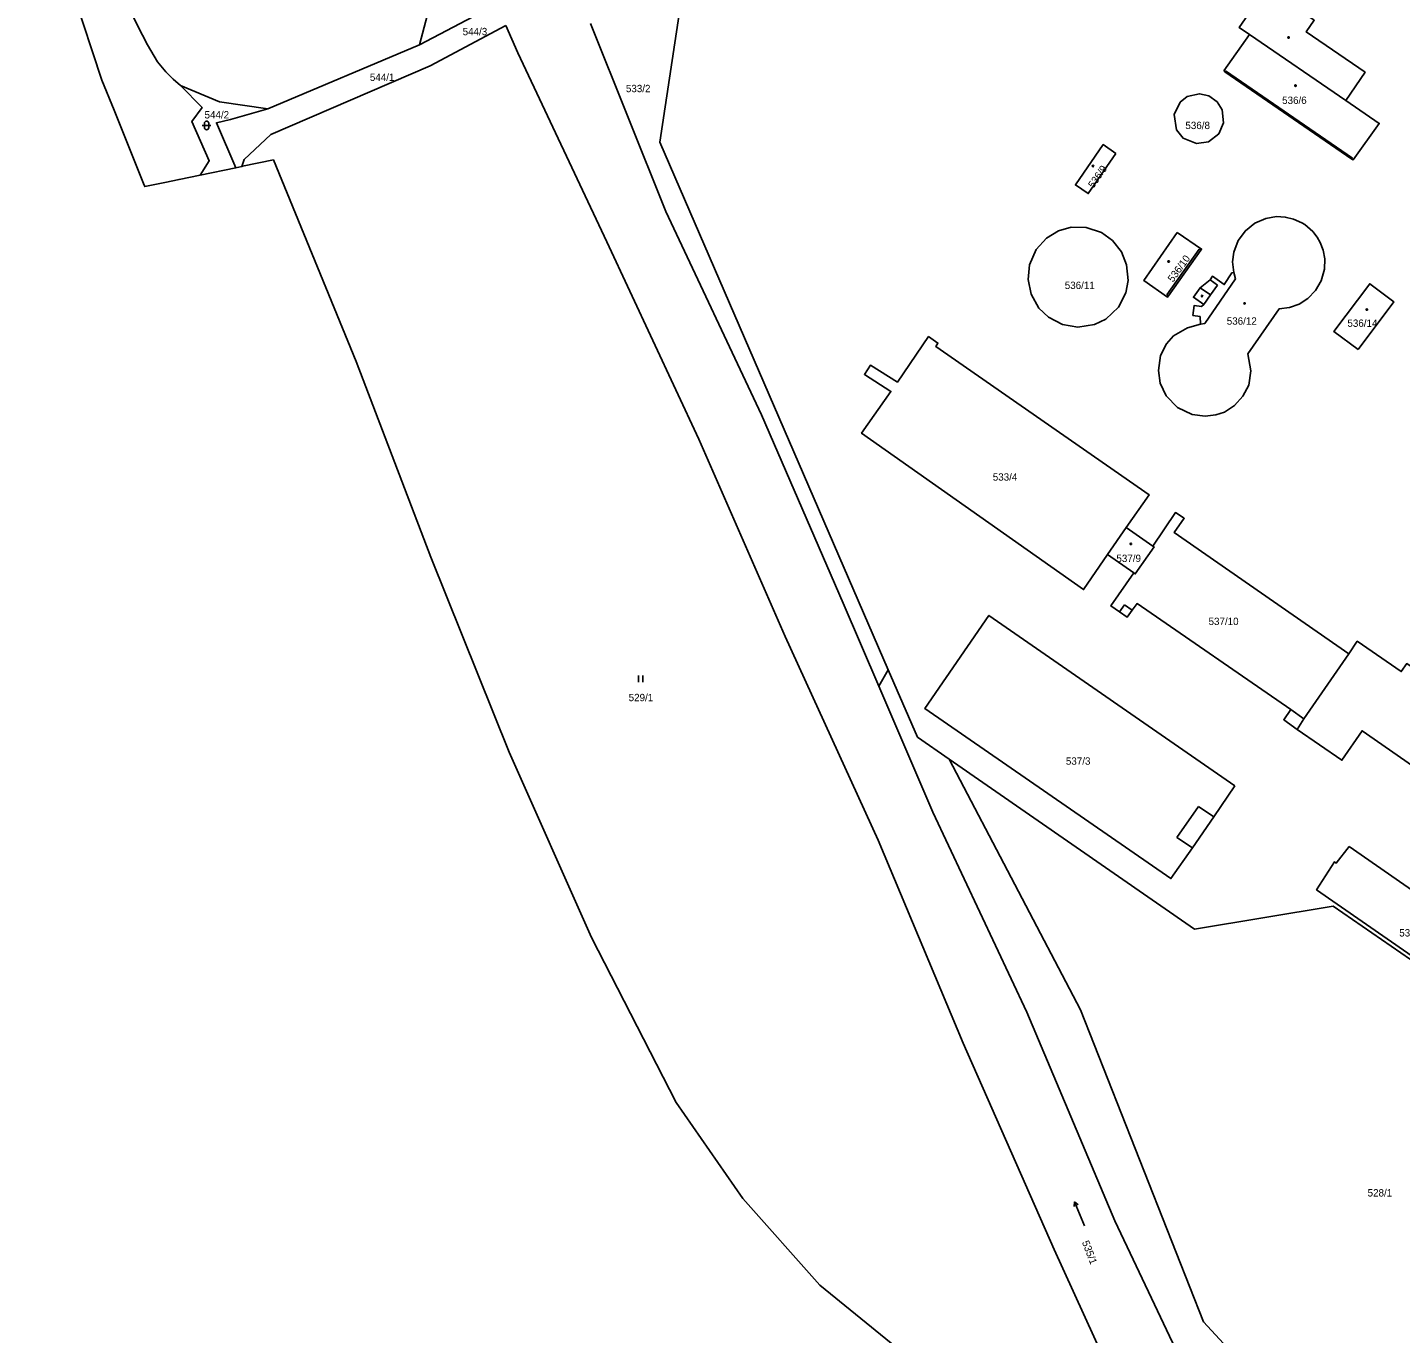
# Model space of a CAD drawing. Extents: x -757266 to -753360, y -1162585 to -1157740.
# Drawn here: x -756709.6 to -756391.6, y -1161803.6 to -1161501.2 of the extents above; entities that cross this region are included whole.
import ezdxf

# ---------------------------------------------------------------- set-up
doc = ezdxf.new("R2010")
doc.units = 0
for name, color, linetype in [('Hranice kat_území', 7, 'Continuous'), ('Hranice parcel', 7, 'Continuous'), ('Parcelní čísla', 7, 'Continuous'), ('Vnitřní kresba', 7, 'Continuous'), ('Značky budov', 7, 'Continuous'), ('Značky kultur', 7, 'Continuous')]:
    doc.layers.add(name, color=color, linetype=linetype)

msp = doc.modelspace()

# ---------------------------------------------------------------- linework, layer by layer
at = {"layer": 'Hranice kat_území'}
msp.add_lwpolyline([(-756705.49, -1161473.54), (-756692.4, -1161513.44), (-756689.53, -1161520.37), (-756682.73, -1161537.36), (-756682.45, -1161538.05), (-756677.8, -1161537.09), (-756674.5, -1161536.4), (-756669.59, -1161535.39), (-756661.38, -1161533.69), (-756659.97, -1161533.4), (-756659.78, -1161533.36), (-756652.63, -1161531.88), (-756633.52, -1161578.59), (-756616.19, -1161623.87), (-756598.04, -1161669), (-756578.96, -1161711.91), (-756559.4, -1161750.12), (-756543.9, -1161772.36), (-756526.13, -1161792.42), (-756501.3, -1161812.53)], dxfattribs=at)
at = {"layer": 'Hranice parcel'}
for p, q in [((-756661.38, -1161533.69), (-756669.59, -1161535.39)), ((-756661.38, -1161533.69), (-756659.97, -1161533.4)), ((-756459.47, -1161623.24), (-756455.15, -1161617)), ((-756455.15, -1161617), (-756449.01, -1161621.28)), ((-756453.34, -1161627.49), (-756459.47, -1161623.24)), ((-756512.46, -1161653.75), (-756510.26, -1161649.92))]:
    msp.add_line(p, q, dxfattribs=at)
for points in [[(-756705.19, -1161454.84), (-756689.73, -1161487.77), (-756688.29, -1161491.6), (-756686.38, -1161496.2), (-756684.14, -1161500.75), (-756681.78, -1161505.2), (-756679.51, -1161509.19), (-756677.58, -1161511.45), (-756675.83, -1161513.16), (-756674.17, -1161514.67)], [(-756709.61, -1161464.59), (-756705.49, -1161473.54), (-756692.4, -1161513.44)], [(-756510.26, -1161649.92), (-756563.14, -1161527.74), (-756558.03, -1161493.93)], [(-756432.53, -1161511.28), (-756426.61, -1161502.85), (-756428.99, -1161501.19), (-756424.46, -1161494.61), (-756421.81, -1161496.44), (-756419.95, -1161493.81), (-756411.59, -1161499.53), (-756413.45, -1161502.24), (-756399.82, -1161511.57), (-756404.28, -1161518.1), (-756396.55, -1161523.42), (-756402.6, -1161531.88), (-756402.85, -1161531.71), (-756432.29, -1161511.45), (-756432.53, -1161511.28)], [(-756653.91, -1161520.08), (-756618.83, -1161505.23), (-756600.13, -1161495.47), (-756599.68, -1161495.24)], [(-756579.23, -1161500.29), (-756561.73, -1161543.82), (-756539.64, -1161590.93), (-756520.71, -1161634.54), (-756512.46, -1161653.75)], [(-756598.79, -1161500.79), (-756616.34, -1161510.09), (-756653.26, -1161525.99), (-756659.39, -1161531.76), (-756659.97, -1161533.4)], [(-756406.05, -1161891.27), (-756403.92, -1161889.19), (-756422.71, -1161865.72), (-756443.95, -1161842.26), (-756451.04, -1161829.66), (-756471.86, -1161784.15), (-756492.92, -1161736.36), (-756512.6, -1161689.34), (-756534.1, -1161642.21), (-756554.15, -1161596.51), (-756575.39, -1161550.85), (-756596.01, -1161507.08), (-756598.79, -1161500.79)], [(-756692.4, -1161513.44), (-756689.53, -1161520.37), (-756682.73, -1161537.36), (-756682.45, -1161538.05), (-756677.8, -1161537.09), (-756674.5, -1161536.4), (-756669.59, -1161535.39)], [(-756653.91, -1161520.08), (-756665.16, -1161518.44), (-756674.17, -1161514.67)], [(-756674.17, -1161514.67), (-756669.18, -1161519.74), (-756671.58, -1161522.96), (-756667.52, -1161532.13), (-756669.59, -1161535.39)], [(-756444.01, -1161521.34), (-756442.65, -1161518.54), (-756440.99, -1161517.23), (-756438.16, -1161516.57), (-756435.97, -1161517.07), (-756434.1, -1161518.4), (-756432.93, -1161520.32), (-756432.62, -1161523.32), (-756433.69, -1161525.81), (-756436.06, -1161527.66), (-756438.89, -1161528.1), (-756441.98, -1161526.82), (-756443.49, -1161524.92), (-756444.01, -1161521.34)], [(-756653.91, -1161520.08), (-756662.59, -1161522.51), (-756665.85, -1161523.27), (-756661.38, -1161533.69)], [(-756457.52, -1161530.41), (-756463.95, -1161539.67), (-756466.9, -1161537.65), (-756460.45, -1161528.34), (-756457.52, -1161530.41)], [(-756652.63, -1161531.88), (-756659.78, -1161533.36), (-756659.97, -1161533.4)], [(-756469.44, -1161834.41), (-756501.3, -1161812.53), (-756526.13, -1161792.42), (-756543.9, -1161772.36), (-756559.4, -1161750.12), (-756578.96, -1161711.91), (-756598.04, -1161669), (-756616.19, -1161623.87), (-756633.52, -1161578.59), (-756652.63, -1161531.88)], [(-756455.05, -1161556.17), (-756454.7, -1161559.78), (-756455.22, -1161562.63), (-756456.91, -1161565.97), (-756459.89, -1161568.77), (-756462.5, -1161570.02), (-756466.35, -1161570.59), (-756469.87, -1161569.99), (-756473.15, -1161568.31), (-756475.35, -1161566.23), (-756477.16, -1161562.99), (-756477.86, -1161559.53), (-756477.52, -1161556.16), (-756475.98, -1161552.64), (-756473.62, -1161550), (-756470.85, -1161548.31), (-756467.85, -1161547.47), (-756464.4, -1161547.51), (-756460.89, -1161548.69), (-756458.33, -1161550.55), (-756456.25, -1161553.2), (-756455.05, -1161556.17)], [(-756443.25, -1161589.18), (-756445.87, -1161586.52), (-756447.28, -1161583.54), (-756447.67, -1161580.67), (-756447.16, -1161577.2), (-756445.77, -1161574.45), (-756444.15, -1161572.58), (-756440.97, -1161570.72), (-756437.91, -1161569.88), (-756438.04, -1161568.14), (-756439.7, -1161567.9), (-756439.38, -1161565.56), (-756437.72, -1161565.78), (-756437.2, -1161565.34), (-756439.57, -1161563.68), (-756438.03, -1161561.48), (-756435.73, -1161559.63), (-756435.16, -1161558.8), (-756432.45, -1161560.73), (-756430.7, -1161558.04), (-756430.24, -1161557.94), (-756430.49, -1161555.44), (-756430.2, -1161553.25), (-756429.2, -1161550.57), (-756427.55, -1161548.29), (-756425.35, -1161546.53), (-756422.8, -1161545.42), (-756420.33, -1161545.01), (-756418.32, -1161545.12), (-756416.42, -1161545.56), (-756414.43, -1161546.41), (-756413.75, -1161546.85), (-756411.94, -1161548.43), (-756410.9, -1161549.76), (-756410.21, -1161550.99), (-756409.49, -1161552.78), (-756409.12, -1161554.78), (-756409.22, -1161557.17), (-756409.98, -1161559.88), (-756411.29, -1161562.15), (-756413.06, -1161563.99), (-756415.07, -1161565.26), (-756417.3, -1161566.07), (-756419.75, -1161566.39), (-756426.95, -1161576.81), (-756426.28, -1161580.73), (-756426.76, -1161584.06), (-756428.11, -1161586.6), (-756430.06, -1161588.76), (-756432.37, -1161590.26), (-756434.36, -1161590.93), (-756436.83, -1161591.24), (-756439.85, -1161590.86), (-756443.25, -1161589.18)], [(-756443.33, -1161548.72), (-756437.7, -1161552.54), (-756437.89, -1161552.81), (-756445.38, -1161563.37), (-756445.57, -1161563.64), (-756451.09, -1161559.77), (-756443.33, -1161548.72)], [(-756401.44, -1161575.8), (-756407.02, -1161571.62), (-756398.74, -1161560.55), (-756393.13, -1161564.74), (-756401.44, -1161575.8)], [(-756455.15, -1161617), (-756449.85, -1161609.39), (-756499.23, -1161575.1), (-756498.76, -1161574.29), (-756500.9, -1161572.8), (-756508.12, -1161583.3), (-756514.34, -1161579.39), (-756515.77, -1161581.53), (-756509.63, -1161585.49), (-756516.41, -1161595.17), (-756465.01, -1161631.37), (-756459.47, -1161623.24)], [(-756449.01, -1161621.28), (-756443.75, -1161613.53), (-756441.71, -1161614.85), (-756444.03, -1161618.17), (-756403.55, -1161646.22)], [(-756453.34, -1161627.49), (-756453.03, -1161627.72), (-756448.7, -1161621.5), (-756449.01, -1161621.28)], [(-756415.55, -1161663.73), (-756418.66, -1161661.5), (-756417.04, -1161659.12), (-756452.61, -1161634.62), (-756453.77, -1161636.14), (-756454.88, -1161637.71), (-756456.67, -1161636.49), (-756458.7, -1161635.14), (-756453.34, -1161627.49)], [(-756429.98, -1161676.77), (-756434.82, -1161684), (-756439.81, -1161691.19), (-756444.79, -1161698.28), (-756501.81, -1161658.88), (-756486.94, -1161637.35), (-756429.98, -1161676.77)], [(-756403.55, -1161646.22), (-756401.63, -1161643.34), (-756391.45, -1161650.36), (-756390.15, -1161648.48), (-756373.68, -1161659.86), (-756371.23, -1161656.38), (-756366.82, -1161659.39), (-756369.21, -1161662.95), (-756349.76, -1161676.41), (-756360.41, -1161691.89), (-756400.5, -1161664.05), (-756405.19, -1161670.87), (-756415.55, -1161663.73)], [(-756403.55, -1161646.22), (-756413.98, -1161661.26), (-756415.55, -1161663.73)], [(-756510.26, -1161649.92), (-756503.51, -1161665.52), (-756496.18, -1161670.6)], [(-756394.07, -1161877.95), (-756411.35, -1161855.64), (-756427.03, -1161838.58), (-756437.34, -1161820.63), (-756457.78, -1161777.52), (-756478.19, -1161729.21), (-756499.94, -1161682.92), (-756512.46, -1161653.75)], [(-756496.18, -1161670.6), (-756465.75, -1161728.65), (-756437.23, -1161800.9), (-756431.67, -1161806.91), (-756424.75, -1161806.95), (-756415.81, -1161824.54), (-756417.35, -1161828.46), (-756403.52, -1161852.63), (-756390.1, -1161864.08), (-756386.3, -1161867.32)], [(-756376.45, -1161723.95), (-756378.08, -1161724.72), (-756407.17, -1161704.66), (-756439.3, -1161710.01), (-756496.18, -1161670.6)], [(-756403.49, -1161690.82), (-756371.84, -1161712.83), (-756374.43, -1161716.92), (-756374.03, -1161717.21), (-756378.36, -1161723.56), (-756411.05, -1161700.86), (-756406.92, -1161694.42), (-756406.53, -1161694.73), (-756403.49, -1161690.82)]]:
    msp.add_lwpolyline(points, dxfattribs=at)
at = {"layer": 'Vnitřní kresba'}
for p, q in [((-756615.95, -1161494.39), (-756618.83, -1161505.23)), ((-756426.61, -1161502.85), (-756404.28, -1161518.1)), ((-756432.29, -1161511.45), (-756432.14, -1161511.22)), ((-756432.14, -1161511.22), (-756402.71, -1161531.5)), ((-756402.85, -1161531.71), (-756402.71, -1161531.5)), ((-756445.75, -1161563.1), (-756438.26, -1161552.55)), ((-756438.26, -1161552.55), (-756437.89, -1161552.81)), ((-756436.92, -1161569.77), (-756429.8, -1161559.43)), ((-756435.73, -1161559.63), (-756434.02, -1161560.88)), ((-756434.02, -1161560.88), (-756435.58, -1161563.08)), ((-756429.8, -1161559.43), (-756430.24, -1161557.94)), ((-756445.38, -1161563.37), (-756445.75, -1161563.1)), ((-756435.58, -1161563.08), (-756438.03, -1161561.48)), ((-756435.58, -1161563.08), (-756437.2, -1161565.34)), ((-756437.91, -1161569.88), (-756436.92, -1161569.77)), ((-756456.67, -1161636.49), (-756455.55, -1161634.9)), ((-756455.55, -1161634.9), (-756453.77, -1161636.14)), ((-756417.04, -1161659.12), (-756413.98, -1161661.26)), ((-756443.38, -1161688.75), (-756438.39, -1161681.56)), ((-756438.39, -1161681.56), (-756434.82, -1161684)), ((-756439.81, -1161691.19), (-756443.38, -1161688.75))]:
    msp.add_line(p, q, dxfattribs=at)
at = {"layer": 'Značky budov'}
for centre in [(-756417.5368, -1161503.5392), (-756415.9368, -1161514.6692), (-756462.8468, -1161533.2892), (-756445.3268, -1161555.3992), (-756437.5568, -1161563.3992), (-756427.7268, -1161565.1092), (-756399.4068, -1161566.5292), (-756454.0668, -1161620.7792)]:
    msp.add_circle(centre, 0.175, dxfattribs=at)
at = {"layer": 'Značky kultur'}
for p, q in [((-756669.121, -1161523.891), (-756667.119, -1161523.891)), ((-756668.621, -1161523.391), (-756668.621, -1161524.392)), ((-756667.619, -1161524.392), (-756667.619, -1161523.391)), ((-756568.081, -1161652.79), (-756568.081, -1161651.29)), ((-756567.08, -1161652.79), (-756567.08, -1161651.29)), ((-756467.082, -1161773.119), (-756467.181, -1161774.213)), ((-756464.835, -1161778.682), (-756467.082, -1161773.119)), ((-756467.082, -1161773.119), (-756466.251, -1161773.838))]:
    msp.add_line(p, q, dxfattribs=at)
for centre, start, end in [((-756668.12, -1161523.3909), 0, 180), ((-756668.12, -1161524.3909), 180, 359.987886)]:
    msp.add_arc(centre, 0.5, start, end, dxfattribs=at)

# ---------------------------------------------------------------- texts
at = {"layer": 'Parcelní čísla'}
for s, p in [('544/3', (-756608.818, -1161503.01)), ('544/1', (-756630.31, -1161513.59)), ('533/2', (-756571.01, -1161516.2)), ('536/6', (-756419.03, -1161518.92)), ('544/2', (-756668.6, -1161522.28)), ('536/8', (-756441.43, -1161524.74)), ('536/11', (-756469.37, -1161561.76)), ('536/12', (-756431.85, -1161570.03)), ('536/14', (-756403.91, -1161570.53)), ('533/4', (-756486.04, -1161606.14)), ('537/9', (-756457.41, -1161624.98)), ('537/10', (-756436.07, -1161639.57)), ('529/1', (-756570.37, -1161657.2)), ('537/3', (-756469.11, -1161671.91)), ('537/13', (-756391.9, -1161711.68)), ('528/1', (-756399.23, -1161771.88))]:
    msp.add_text(s, height=1.7, dxfattribs=at).set_placement(p)
for s, rotation, p in [('536/9', 55, (-756462.723, -1161538.557)), ('536/10', 54, (-756444.302, -1161560.329)), ('535/1', 290.999997, (-756465.423, -1161782.454))]:
    msp.add_text(s, height=1.7, rotation=rotation, dxfattribs=at).set_placement(p)

doc.saveas('drawing.dxf')
